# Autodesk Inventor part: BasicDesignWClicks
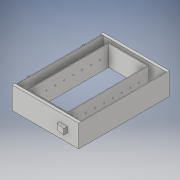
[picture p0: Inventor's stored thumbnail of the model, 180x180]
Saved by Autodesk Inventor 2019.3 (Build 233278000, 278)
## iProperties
Created: 2019-10
Part Number: BasicDesignWClicks
Material: Generic
Document SubType Name: Modeling
Designer: KrystynWikoff
Density: 1 g/cm^3
Appearance: Default
Author: KrystynWikoff
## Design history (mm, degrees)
sketch "Sketch1"
  geometry: L1 (0, 0)-(304.8, 0); L2 (304.8, 0)-(304.8, -416.56); L3 (304.8, -416.56)-(0, -416.56); L4 (0, -416.56)-(0, 0)
  constraints: 8 end point, 2 parallel, 1 horizontal, 1 perpendicular
  dimensions: "d0" = 416.56 distance of L3.end L1.start; "d1" = 304.8 distance of L1.start L1.end
extrude "Extrusion1" new body sketch "Sketch1" distance "d2" = 101.6; taper "d3" = 0 deg
sketch "Sketch2"
  geometry: L1 (-76.2, 25.4)-(-254, 25.4); L2 (-254, 25.4)-(-254, 391.16); L3 (-254, 391.16)-(-76.2, 391.16); L4 (-76.2, 391.16)-(-76.2, 25.4); L5 (0, 0)-(0, 416.56) reference; L6 (-304.8, 416.56)-(-304.8, 0) reference; L7 (-304.8, 0)-(0, 0) reference; L8 (0, 416.56)-(-304.8, 416.56) reference
  constraints: 8 end point, 2 parallel, 1 horizontal, 1 perpendicular
  dimensions: "d4" = 76.2 distance between parallel lines of L5 L4; "d5" = 50.8 distance between parallel lines of L2 L6; "d6" = 25.4 distance between parallel lines of L7 L1; "d7" = 25.4 distance between parallel lines of L8 L3
extrude "Extrusion2" cut sketch "Sketch2" distance "d8" = 101.6; taper "d9" = 0 deg
shell "Shell1" dims "d10" = 3.175
sketch "Sketch3" dims "d19" = 25.4
  geometry: L1 (0, 0)-(0, -101.6) reference; L2 (0, 0)-(365.76, 0) reference; C1 r 2.54 at (40.64, -50.8); C2 r 2.54 at (81.28, -50.8); C3 r 2.54 at (121.92, -50.8); C4 r 2.54 at (162.56, -50.8); C5 r 2.54 at (203.2, -50.8); C6 r 2.54 at (243.84, -50.8); C7 r 2.54 at (284.48, -50.8); C8 r 2.54 at (325.12, -50.8); 1 further point
  constraints: 8 centre point, 1 horizontal, 14 other
  dimensions: "d11" = 5.08 diameter of C1; "d12" = 40.64 distance from line of L1 C1.centre; "d13" = 50.8 distance from line of C1.centre L2; "d16" = 40.64 distance of C1.centre C2.centre
extrude "Extrusion3" cut sketch "Sketch3" distance "d21" = 3.175; taper "d22" = 0 deg
sketch "Sketch4" dims "d31" = 25.4
  geometry: L1 (0, 0)-(0, -101.6) reference; L2 (0, 0)-(365.76, 0) reference; C1 r 2.54 at (40.64, -50.8); C2 r 2.54 at (81.28, -50.8); C3 r 2.54 at (121.92, -50.8); C4 r 2.54 at (162.56, -50.8); C5 r 2.54 at (203.2, -50.8); C6 r 2.54 at (243.84, -50.8); C7 r 2.54 at (284.48, -50.8); C8 r 2.54 at (325.12, -50.8); 1 further point
  constraints: 8 centre point, 1 horizontal, 14 other
  dimensions: "d23" = 5.08 diameter of C1; "d24" = 40.64 distance from line of C1.centre L1; "d25" = 50.8 distance from line of L2 C1.centre; "d28" = 40.64 distance of C1.centre C2.centre
extrude "Extrusion4" cut sketch "Sketch4" distance "d33" = 3.175; taper "d34" = 0 deg
sketch "Sketch5" dims "d43" = 25.4
  geometry: L1 (0, 101.6)-(304.8, 101.6) reference; L2 (0, 0)-(0, 101.6) reference; C1 r 19.05 at (50.8, 50.8); C2 r 19.05 at (101.6, 50.8)
  constraints: 2 centre point, 1 horizontal, 2 other
  dimensions: "d35" = 38.1 diameter of C1; "d36" = 50.8 distance from line of L1 C1.centre; "d37" = 50.8 distance from line of C1.centre L2; "d40" = 50.8 distance of C1.centre C2.centre
extrude "Extrusion5" join sketch "Sketch5" distance "d45" = 19.05; taper "d46" = 0 deg
sketch "Sketch6"
  geometry: L1 (215.9, 38.1)-(254, 38.1); L2 (254, 38.1)-(254, 63.5); L3 (254, 63.5)-(215.9, 63.5); L4 (215.9, 63.5)-(215.9, 38.1); L5 (304.8, 0)-(0, 0) reference; L6 (0, 101.6)-(304.8, 101.6) reference; L7 (304.8, 0)-(304.8, 101.6) reference
  constraints: 8 end point, 2 parallel, 1 horizontal, 1 perpendicular
  dimensions: "d47" = 38.1 distance between parallel lines of L5 L1; "d48" = 38.1 distance from line of L6 L2.end; "d49" = 50.8 distance between parallel lines of L7 L2; "d50" = 38.1 distance between parallel lines of L2 L4
extrude "Extrusion6" join sketch "Sketch6" distance "d51" = 19.05; taper "d52" = 0 deg
sketch "Sketch7"
  geometry: L1 (0, 0)-(0, 19.05) reference; L2 (0, 9.525)-(39.688, 19.05); L3 (39.688, 19.05)-(0, 19.05); L4 (0, 19.05)-(0, 9.525); 1 further point
  constraints: 6 end point, 1 collinear, 1 midpoint, 1 perpendicular
extrude "Extrusion7" cut sketch "Sketch7" distance "d53" = 25.4; taper "d54" = 0 deg
sketch "Sketch8"
  geometry: L1 (0, -416.56)-(0, 0) reference; L2 (-304.8, -416.56)-(0, -416.56) reference; L3 (0, 0)-(-304.8, 0) reference; L4 (-292.1, -242.57)-(-266.7, -242.57); L5 (-266.7, -242.57)-(-266.7, -173.99); L6 (-266.7, -173.99)-(-292.1, -173.99); L7 (-292.1, -173.99)-(-292.1, -242.57); L8 (-304.8, 0)-(-304.8, -416.56) reference; C1 r 12.7 at (-38.1, -391.16); C2 r 12.7 at (-38.1, -25.4)
  constraints: 8 end point, 2 centre point, 2 parallel, 1 horizontal, 1 perpendicular
  dimensions: "d55" = 25.4 diameter of C1; "d56" = 38.1 distance from line of L1 C1.centre; "d57" = 25.4 distance from line of L2 C1.centre; "d58" = 25.4 diameter of C2; "d59" = 25.4 distance from line of L3 C2.centre; "d60" = 38.1 distance from line of L1 C2.centre; "d61" = 25.4 distance of L4.start L4.end; "d62" = 68.58 distance of L6.end L4.start; "d63" = 173.99 distance between parallel lines of L4 L2; "d64" = 12.7 distance between parallel lines of L8 L7
extrude "Extrusion8" cut sketch "Sketch8" extent not by distance; stored distance "d65" = 2.54; taper "d66" = 0 deg
sketch "Sketch9"
  geometry: C1 r 2.54 at (325.12, -50.8) reference; C2 r 2.54 at (325.12, -50.8); 1 further point
  constraints: 1 centre point, 1 coincident
extrude "Extrusion9" join sketch "Sketch9" distance "d67" = 177.8; taper "d68" = 0 deg
pattern_linear "Rectangular Pattern1" dims "d71" = 40.64
sketch "Sketch10"
  geometry: L1 (76.2, 88.9)-(88.9, 88.9); L2 (88.9, 88.9)-(88.9, 82.55); L3 (88.9, 82.55)-(76.2, 82.55); L4 (76.2, 82.55)-(76.2, 88.9); L5 (0, 101.6)-(416.56, 101.6) reference; L6 (0, 0)-(0, 101.6) reference; L7 (391.16, 101.6)-(25.4, 101.6) reference; L8 (208.28, 101.6)-(208.28, 38.1); L9 (340.36, 88.9)-(327.66, 88.9); L10 (327.66, 88.9)-(327.66, 82.55); L11 (327.66, 82.55)-(340.36, 82.55); L12 (340.36, 82.55)-(340.36, 88.9); 1 further point
  constraints: 18 end point, 4 symmetric about line, 2 parallel, 1 horizontal, 1 midpoint, 1 perpendicular, 1 vertical
  dimensions: "d72" = 12.7 distance between parallel lines of L5 L1; "d73" = 76.2 distance between parallel lines of L6 L4; "d74" = 12.7 distance of L2.end L3.end; "d75" = 6.35 distance of L1.end L2.end
extrude "Extrusion10" join sketch "Sketch10" distance "d76" = 8.382; taper "d77" = 0 deg
sketch "Sketch11"
  geometry: L1 (-6.795, 1.587)-(-1.587, 1.587); L2 (-1.587, 1.587)-(-1.587, 11.113); L3 (-1.587, 11.113)-(-6.795, 11.113); L4 (-6.795, 11.113)-(-6.795, 1.587); L5 (0, 12.7)-(-8.382, 12.7) reference; L6 (0, 0)-(-8.382, 0) reference; L7 (-8.382, 0)-(-8.382, 12.7) reference; L8 (0, 88.9)-(0, -327.66) reference; L9 (-6.795, -249.872)-(-1.587, -249.872); L10 (-1.587, -249.872)-(-1.588, -240.347); L11 (-1.588, -240.347)-(-6.795, -240.347); L12 (-6.795, -240.347)-(-6.795, -249.872); L13 (-8.382, -251.46)-(-8.382, -238.76) reference; L14 (0, -251.46)-(-8.382, -251.46) reference; L15 (0, -238.76)-(-8.382, -238.76) reference; 1 further point
  constraints: 16 end point, 4 parallel, 2 horizontal, 2 perpendicular
  dimensions: "d78" = 1.5875 distance between parallel lines of L5 L3; "d79" = 1.5875 distance between parallel lines of L6 L1; "d80" = 1.5875 distance between parallel lines of L7 L4; "d81" = 1.5875 distance between parallel lines of L8 L2; "d82" = 1.5875 distance between parallel lines of L13 L12; "d83" = 1.5875 distance between parallel lines of L8 L10; "d84" = 1.5875 distance between parallel lines of L14 L9; "d85" = 1.5875 distance between parallel lines of L15 L11
extrude "Extrusion11" cut sketch "Sketch11" distance "d86" = 8.382; taper "d87" = 0 deg
sketch "Sketch12"
  geometry: L1 (416.56, 101.6)-(0, 101.6) reference; L2 (0, 101.6)-(12.7, 101.6); L3 (12.7, 101.6)-(3.175, 95.25); L4 (3.175, 3.175)-(3.175, 101.6) reference; L5 (3.175, 101.6)-(3.175, 95.25); L6 (25.4, 101.6)-(391.16, 101.6) reference; L7 (208.28, 101.6)-(208.28, 0); L8 (242.57, 0)-(173.99, 0) reference; L9 (0, 101.6)-(416.56, 101.6); L10 (416.56, 101.6)-(403.86, 101.6); L11 (403.86, 101.6)-(413.385, 95.25); L12 (413.385, 3.175)-(413.385, 101.6); L13 (413.385, 101.6)-(413.385, 95.25); 1 further point
  constraints: 18 end point, 6 symmetric about line, 4 point on line, 2 midpoint, 1 collinear
  dimensions: "d88" = 33.6901 deg angle of L1 L3; "d89" = 6.35 vertical distance of L2.end L3.end
extrude "Extrusion12" join sketch "Sketch12" stored distance "d90" = 8.382; taper "d91" = 0 deg
sketch "Sketch13"
  geometry: L1 (0, 101.6)-(416.56, 101.6) reference; L2 (3.175, 95.25)-(12.7, 101.6) reference; L3 (12.7, 101.6)-(3.175, 95.25); L4 (3.175, 95.25)-(413.385, 95.25); L5 (403.86, 101.6)-(413.385, 95.25) reference; L6 (413.385, 95.25)-(403.86, 101.6); L7 (403.86, 101.6)-(12.7, 101.6) reference; L8 (403.86, 101.6)-(12.7, 101.6); 1 further point
  constraints: 8 end point, 3 collinear, 1 horizontal, 1 point on line
extrude "Extrusion13" cut sketch "Sketch13" distance "d92" = 254.4445; taper "d93" = 0 deg
body "Solid1"
